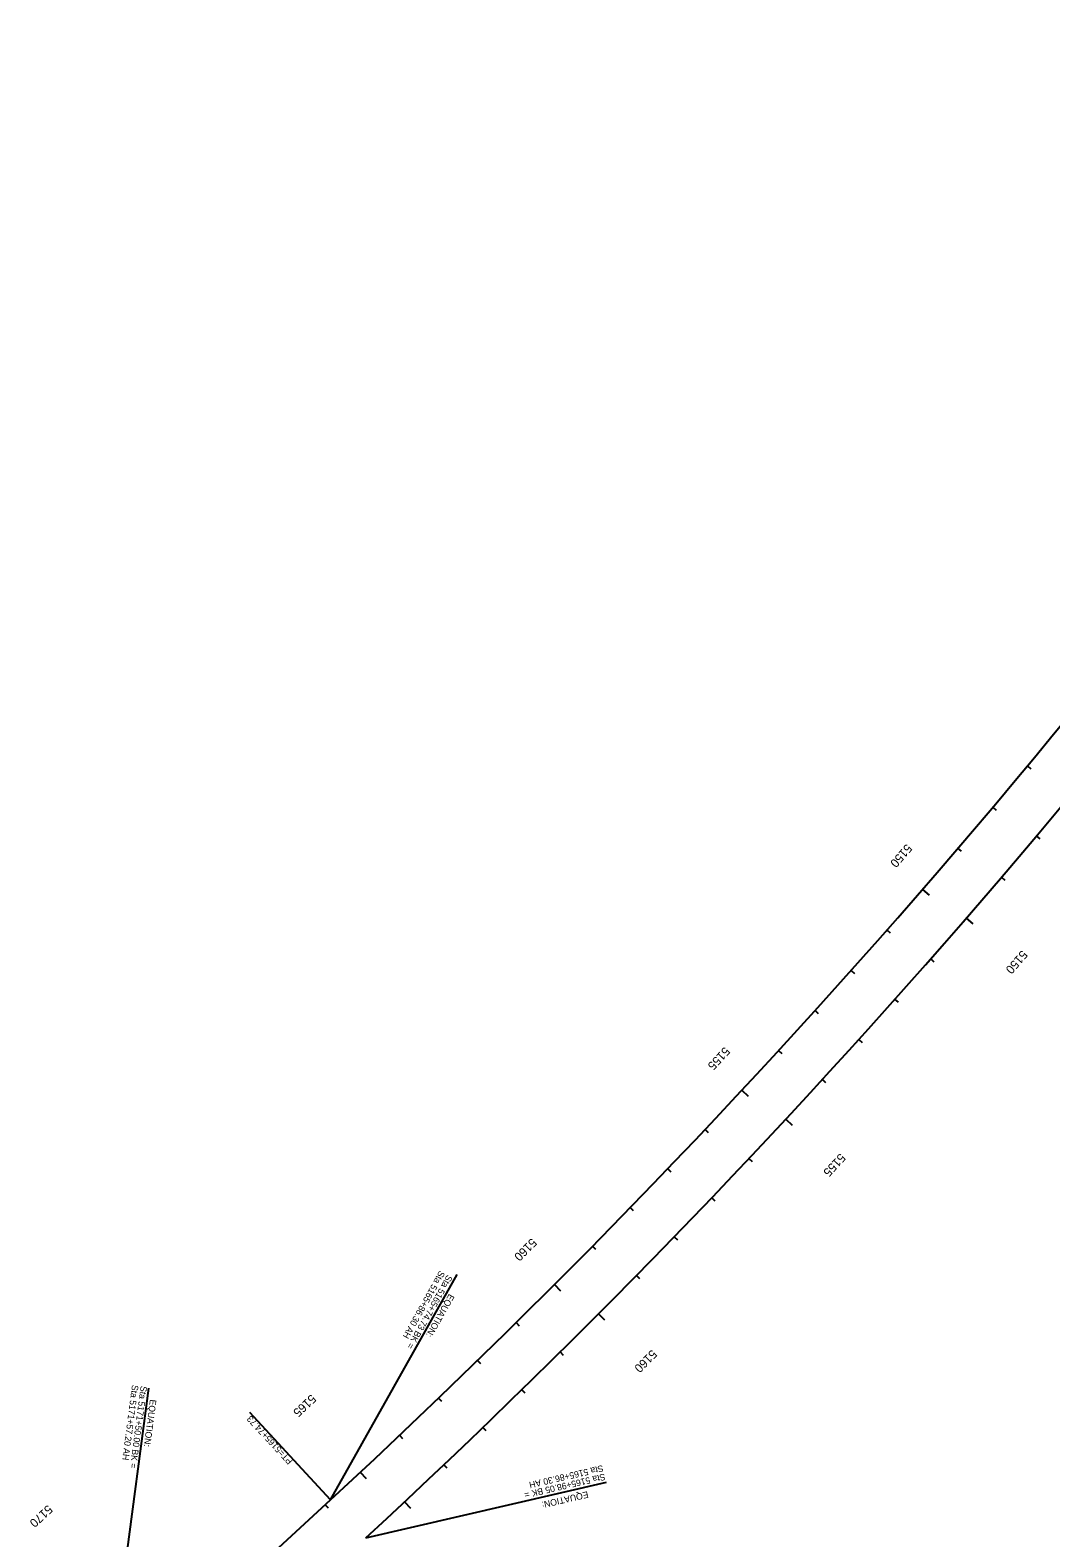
# Model space of a CAD drawing. Extents: x 2160877 to 2175861, y 601747 to 617724.
# Drawn here: x 2172065 to 2173955, y 614087 to 616878 of the extents above; entities that cross this region are included whole.
import ezdxf

# ---------------------------------------------------------------- set-up
doc = ezdxf.new("R2010")
doc.units = 0
for name, color, linetype in [('RD_HC_Cl', 7, 'Continuous'), ('RD_HC_Data', 7, 'Continuous'), ('RD_HC_Data_Tic', 7, 'Continuous'), ('RD_HC_TX_StaOther', 7, 'Continuous')]:
    doc.layers.add(name, color=color, linetype=linetype)

msp = doc.modelspace()

# ---------------------------------------------------------------- linework, layer by layer
at = {"layer": 'RD_HC_Cl'}
msp.add_line((2172621.5, 614157.6), (2172207.3, 613775.1), dxfattribs=at)
for radius, end in [(14276, 327.03525), (14372, 326.23563)]:
    msp.add_arc((2162936.5, 624645.9), radius, 312.71947, end, dxfattribs=at)
at = {"layer": 'RD_HC_Data'}
for p, q in [((2172621.5, 614157.6), (2172855.6, 614574.5)), ((2172207.3, 613775.1), (2172285.1, 614364.1)), ((2172621.5, 614157.6), (2172472.2, 614319.2)), ((2172686.6, 614087), (2173132, 614189.8))]:
    msp.add_line(p, q, dxfattribs=at)
at = {"layer": 'RD_HC_Data_Tic'}
for p, q in [((2173911.5, 615516), (2173917.6, 615510.9)), ((2173847.2, 615439.4), (2173853.3, 615434.2)), ((2173927.9, 615386.2), (2173934.1, 615381)), ((2173782.5, 615363.2), (2173788.6, 615358)), ((2173863.2, 615309.9), (2173869.3, 615304.7)), ((2173717.2, 615287.5), (2173729.3, 615277)), ((2173798, 615234.1), (2173810.1, 615223.7)), ((2173651.4, 615212.2), (2173657.4, 615206.9)), ((2173732.3, 615158.8), (2173738.3, 615153.5)), ((2173585, 615137.3), (2173591, 615132)), ((2173666, 615083.9), (2173672, 615078.6)), ((2173518.2, 615063), (2173524.1, 615057.6)), ((2173599.2, 615009.5), (2173605.1, 615004.1)), ((2173450.8, 614989.1), (2173456.7, 614983.7)), ((2173531.9, 614935.5), (2173537.8, 614930.1)), ((2173382.9, 614915.7), (2173394.6, 614904.8)), ((2173464.1, 614862), (2173475.8, 614851.1)), ((2173314.5, 614842.8), (2173320.3, 614837.3)), ((2173245.5, 614770.3), (2173251.3, 614764.8)), ((2173395.8, 614789), (2173401.6, 614783.5)), ((2173326.9, 614716.5), (2173332.7, 614711)), ((2173176.1, 614698.3), (2173181.8, 614692.8)), ((2173257.6, 614644.4), (2173263.3, 614638.9)), ((2173106.2, 614626.8), (2173111.9, 614621.2)), ((2173187.7, 614572.9), (2173193.4, 614567.3)), ((2173035.7, 614555.9), (2173047.1, 614544.5)), ((2173117.4, 614501.8), (2173128.7, 614490.5)), ((2172964.8, 614485.4), (2172970.4, 614479.7)), ((2172893.4, 614415.4), (2172899, 614409.6)), ((2173046.6, 614431.2), (2173052.2, 614425.5)), ((2172975.3, 614361.1), (2172980.8, 614355.4)), ((2172821.5, 614345.9), (2172827, 614340.1)), ((2172749.1, 614276.9), (2172754.6, 614271.1)), ((2172903.5, 614291.5), (2172909, 614285.7)), ((2172831.2, 614222.4), (2172836.7, 614216.6)), ((2172676.2, 614208.4), (2172687.2, 614196.7)), ((2172758.4, 614153.8), (2172769.3, 614142.1)), ((2172611.4, 614148.3), (2172616.8, 614142.4))]:
    msp.add_line(p, q, dxfattribs=at)

# ---------------------------------------------------------------- texts
at = {"layer": 'RD_HC_Data'}
for s, rotation, p in [('Sta 5165+86.30 AH', 240.6833, (2172823.3, 614582.6)), ('Sta 5165+74.73 BK = ', 240.6833, (2172837.3, 614574.8)), ('EQUATION:', 240.6833, (2172840.9, 614539.6)), ('Sta 5171+57.20 AH', 262.4748, (2172254.1, 614370.8)), ('Sta 5171+50.00 BK = ', 262.4748, (2172270, 614368.7)), ('EQUATION:', 262.4748, (2172287.3, 614343.8)), ('PT=5165+74.73', 132.7195, (2172552.2, 614229.7)), ('Sta 5165+86.30 AH', 192.9905, (2173124.9, 614221.9)), ('Sta 5165+98.05 BK = ', 192.9905, (2173128.5, 614206.3)), ('EQUATION:', 192.9905, (2173097.1, 614173.4))]:
    msp.add_text(s, height=12, rotation=rotation, dxfattribs=at).set_placement(p)
at = {"layer": 'RD_HC_TX_StaOther'}
for s, rotation, p in [('5150', 229.0396, (2173687.4, 615372.7)), ('5150', 229.0903, (2173901, 615175.8)), ('5155', 227.0328, (2173350.7, 614997)), ('5155', 227.097, (2173564.6, 614799.8)), ('5160', 225.0261, (2172993.6, 614642.8)), ('5160', 225.1037, (2173216, 614436.4)), ('5165', 223.0194, (2172585.6, 614353.6)), ('5170', 222.7195, (2172098, 614149))]:
    msp.add_text(s, height=16, rotation=rotation, dxfattribs=at).set_placement(p)

doc.saveas('drawing.dxf')
